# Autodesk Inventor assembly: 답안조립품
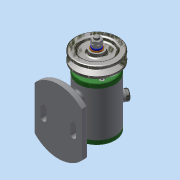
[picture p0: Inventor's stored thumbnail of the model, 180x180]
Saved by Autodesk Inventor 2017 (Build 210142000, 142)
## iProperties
Created: 2022-02
Part Number: 답안조립품
Document SubType Name: Weldment
Designer: 601-07
Weld Material: Welded Aluminum-6061
Author: 601-07
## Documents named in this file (14)
- C:\Users\601-07\Desktop\720206V1006\답안조립품.iam
- C:\Users\601-07\Desktop\720206V1006\본체.ipt
- C:\Users\601-07\Desktop\720206V1006\V벨트풀리.ipt
- C:\Users\601-07\Desktop\720206V1006\고무 캡.ipt
- C:\Users\601-07\Desktop\720206V1006\너트 M8.ipt
- C:\Users\601-07\Desktop\720206V1006\뒤커버.ipt
- C:\Users\601-07\Desktop\720206V1006\베어링 6002.ipt
- C:\Users\601-07\Desktop\720206V1006\볼트 M4 x 10.ipt
- C:\Users\601-07\Desktop\720206V1006\스프링와셔 8.ipt
- C:\Users\601-07\Desktop\720206V1006\앞커버.ipt
- C:\Users\601-07\Desktop\720206V1006\오일 실 15 x 25 x 7.ipt
- C:\Users\601-07\Desktop\720206V1006\축.ipt
- C:\Users\601-07\Desktop\720206V1006\키 3 x 3 x 12.ipt
- C:\Users\601-07\Desktop\720206V1006\평와셔 8 x 17.ipt
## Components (2 placed, 2 different names)
1. V벨트풀리:1
2. 고무 캡:1
